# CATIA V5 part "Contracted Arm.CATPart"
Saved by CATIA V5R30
Part number: AERO2001-Project-Contracted arm
Bounding box of the stored display mesh (mm): x -9.4 to 9.4, y -9.4 to 9.4, z -10 to 13.2
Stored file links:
  D:\OneDrive\OneDrive - Carleton University\Courses\aero2001\Design Project\3D Models\Closed\Contracted Arm.CATPart
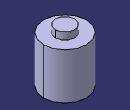
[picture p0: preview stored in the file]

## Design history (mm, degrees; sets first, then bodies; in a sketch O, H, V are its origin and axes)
Body1 (main body)
  Sketch1 on xy-plane, origin (0, 0, 0), H (1, 0, 0), V (0, 1, 0)
    circle A1 centre (0, 0) radius 9.4
    radius A1 = 9.4
  Pad1: profile Sketch1, direction (0, 0, 1), length 10, mirrored extent
  Sketch2 on end face of Pad1, origin (0, 0, 10), H (1, 0, 0), V (0, 1, 0)
    circle A1 centre (0, 0) radius 9.2
    point P1 (0, 9.2)
    radius A1 = 9.2
    coincidence: A1 P1, P1 V
  Pocket1: profile Sketch2, direction (0, 0, -1), length 19.8
  Sketch3 on end face of Pocket1, origin (0, 0, -9.8), H (1, 0, 0), V (0, 1, 0)
    circle A1 centre (0, 0) radius 9.2
    radius A1 = 9.2
  Pad2: profile Sketch3, direction (0, 0, 1), length 20, thin wall 0, second thickness 0.2
  Sketch4 on end face of Pocket1, origin (0, 0, -9.8), H (1, 0, 0), V (0, 1, 0)
    circle A1 centre (0, 0) radius 9
    radius A1 = 9
  Pad3: profile Sketch4, direction (0, 0, 1), length 20, thin wall 0, second thickness 0.2
  Sketch5 on end face of Pocket1, origin (0, 0, -9.8), H (1, 0, 0), V (0, 1, 0)
    circle A1 centre (0, 0) radius 8.8
    radius A1 = 8.8
  Pad4: profile Sketch5, direction (0, 0, 1), length 20, thin wall 0, second thickness 0.2
  Sketch6 on end face of Pocket1, origin (0, 0, -9.8), H (1, 0, 0), V (0, 1, 0)
    circle A1 centre (0, 0) radius 8.6
    radius A1 = 8.6
  Pad5: profile Sketch6, direction (0, 0, 1), length 20, thin wall 0, second thickness 0.2
  Sketch7 on end face of Pocket1, origin (0, 0, -9.8), H (1, 0, 0), V (0, 1, 0)
    circle A1 centre (0, 0) radius 8.4
    radius A1 = 8.4
  Pad6: profile Sketch7, direction (0, 0, 1), length 20, thin wall 0, second thickness 0.2
  Sketch8 on end face of Pocket1, origin (0, 0, -9.8), H (1, 0, 0), V (0, 1, 0)
    circle A1 centre (0, 0) radius 8.2
    radius A1 = 8.2
  Pad7: profile Sketch8, direction (0, 0, 1), length 20, thin wall 0, second thickness 0.2
  Sketch9 on end face of Pocket1, origin (0, 0, -9.8), H (1, 0, 0), V (0, 1, 0)
    circle A1 centre (0, 0) radius 8
    radius A1 = 8
  Pad8: profile Sketch9, direction (0, 0, 1), length 20, thin wall 0, second thickness 0.2
  Sketch10 on end face of Pocket1, origin (0, 0, -9.8), H (1, 0, 0), V (0, 1, 0)
    circle A1 centre (0, 0) radius 7.8
    radius A1 = 7.8
  Pad9: profile Sketch10, direction (0, 0, 1), length 20, thin wall 0, second thickness 0.2
  Sketch11 on end face of Pocket1, origin (0, 0, -9.8), H (1, 0, 0), V (0, 1, 0)
    circle A1 centre (0, 0) radius 7.6
    radius A1 = 7.6
  Pad10: profile Sketch11, direction (0, 0, 1), length 20, thin wall 0, second thickness 0.2
  Sketch12 on end face of Pocket1, origin (0, 0, -9.8), H (1, 0, 0), V (0, 1, 0)
    circle A1 centre (0, 0) radius 4.4
    radius A1 = 4.4
  Pocket2: profile Sketch12, direction (0, 0, 1), length 20
  Sketch13 on face of Pocket2, origin (0, 0, -9.8), H (1, 0, 0), V (0, 1, 0)
    circle A1 centre (0, 0) radius 4.2
    radius A1 = 4.2
  Pad11: profile Sketch13, direction (0, 0, 1), length 20, thin wall 0, second thickness 4.8
  Sketch14 on face of Pocket2, origin (0, 0, -9.8), H (1, 0, 0), V (0, 1, 0)
    circle A1 centre (0, 0) radius 4.2
    radius A1 = 4.2
  Pad12: profile Sketch14, direction (0, 0, 1), length 23
  Sketch15 on xy-plane, origin (0, 0, 0), H (1, 0, 0), V (0, 1, 0)
    circle A1 centre (0, 0) radius 4
    radius A1 = 4
  Pocket3: profile Sketch15, direction (0, 0, 1), length 12.8, opposite side length 9.8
